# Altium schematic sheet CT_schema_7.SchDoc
size 405 x 220 mm
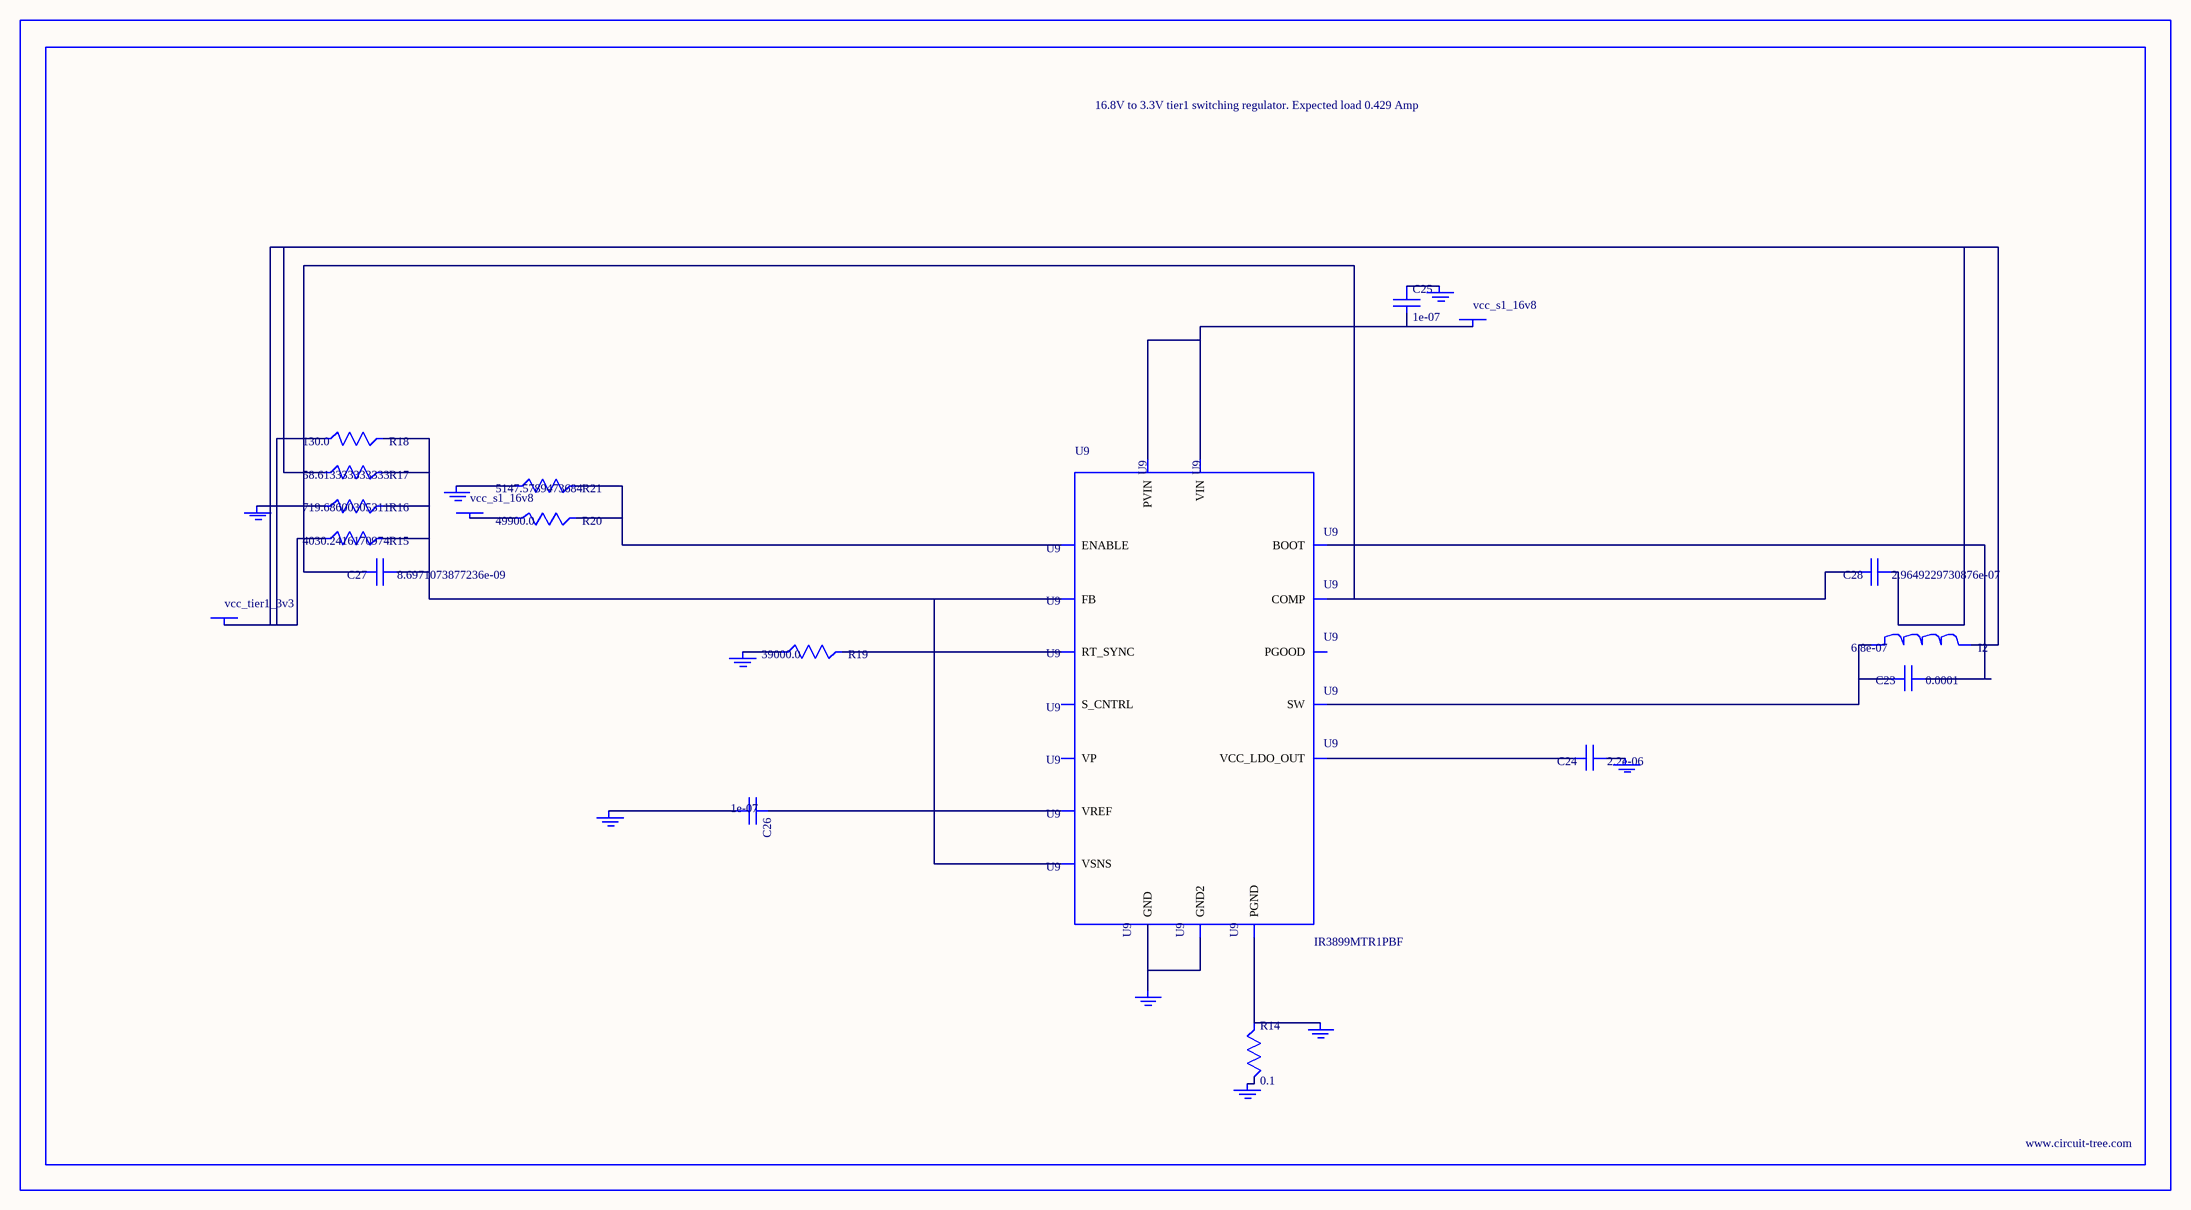
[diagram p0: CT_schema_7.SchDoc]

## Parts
BORDER6  (no value)
C23  0.0001  [C1210]
C24  2.2e-06  [C0603]
C25  1e-07  [C0402]
C26  1e-07  [C0402]
C27  8.6971073877236e-09  [R0603]
C28  2.9649229730876e-07  [R0603]
GND_INSTANCE_6_0  (no value)
GND_INSTANCE_6_1  (no value)
GND_INSTANCE_6_2  (no value)
GND_INSTANCE_6_3  (no value)
GND_INSTANCE_6_4  (no value)
GND_INSTANCE_6_5  (no value)
GND_INSTANCE_6_6  (no value)
GND_INSTANCE_6_7  (no value)
GND_INSTANCE_6_8  (no value)
I2  6.8e-07  [IND25X25CZ]
POWER_INSTANCE_6_0  vcc_s1_16v8
POWER_INSTANCE_6_1  vcc_s1_16v8
POWER_INSTANCE_6_2  vcc_tier1_3v3
R14  0.1  [R0603]
R15  4030.2416170974  [R0603]
R16  719.68600305311  [R0603]
R17  58.613333333333  [R0603]
R18  130.0  [R0603]
R19  39000.0  [R0603]
R20  49900.0  [R0603]
R21  5147.5789473684  [R0603]
U9  IR3899MTR1PBF  [IR3899MTR1PBF]

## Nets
NetC23_1: C23.1 U9.14(BOOT)
NetC23_2: C23.2 I2.1 U9.12(SW)
NetC24_1: C24.1 GND_INSTANCE_6_4.0(GND)
NetC24_2: C24.2 U9.10(VCC_LDO_OUT)
NetC25_1: C25.1 GND_INSTANCE_6_3.0(GND)
NetC25_2: C25.2 POWER_INSTANCE_6_0.0(PWR) U9.9(VIN) U9.13(PVIN)
NetC26_1: C26.1 U9.2(VREF)
NetC26_2: C26.2 GND_INSTANCE_6_1.0(GND)
NetC27_1: C27.1 R15.2 R16.2 R17.2 R18.2 U9.1(FB) U9.8(VSNS)
NetC27_2: C27.2 C28.2 U9.3(COMP)
NetC28_1: C28.1 I2.2 POWER_INSTANCE_6_2.0(PWR) R15.1 R17.1 R18.1
NetGND_INSTANCE_6_0_0: GND_INSTANCE_6_0.0(GND) R16.1
NetGND_INSTANCE_6_2_0: GND_INSTANCE_6_2.0(GND) R19.1
NetGND_INSTANCE_6_5_0: GND_INSTANCE_6_5.0(GND) R14.2
NetGND_INSTANCE_6_6_0: GND_INSTANCE_6_6.0(GND) R14.1 U9.11(PGND)
NetGND_INSTANCE_6_7_0: GND_INSTANCE_6_7.0(GND) R21.1
NetGND_INSTANCE_6_8_0: GND_INSTANCE_6_8.0(GND) U9.4(GND) U9.17(GND2)
NetPOWER_INSTANCE_6_1_0: POWER_INSTANCE_6_1.0(PWR) R20.1
NetR19_2: R19.2 U9.5(RT_SYNC)
NetR20_2: R20.2 R21.2 U9.15(ENABLE)

Not connected (* = marked no-connect by the designer): U9 6(S_CNTRL) 7(PGOOD) 16(VP)

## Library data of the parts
BORDER6 = BORDER_PAGE6
C23 = GRM32ER61A107ME20L
C24 = C0603C225K8RACTU
C25 C26 = C0402C104K3RACTU
C27 = C27
C28 = C28
GND_INSTANCE_6_0-GND_INSTANCE_6_8 = GND
I2 = IHLP2525CZERR68M01
POWER_INSTANCE_6_0-POWER_INSTANCE_6_2 = PWR
R14 = ERJ-3RSFR10V
R15 = R15
R16 = R16
R17 = R17
R18 = RC0603JR-07130RL
R19 = RC0603JR-0739KL
R20 = RC0603FR-0749K9
R21 = R21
